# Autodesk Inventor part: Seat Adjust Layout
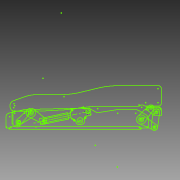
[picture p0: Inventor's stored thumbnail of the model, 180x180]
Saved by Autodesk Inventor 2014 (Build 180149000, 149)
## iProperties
Created: 2008-08
Part Number: Seat Adjust Layout
Document SubType Name: Modeling
Designer: hendert
Density: 1 g/cm^3
Material: Generic
Appearance: Default
d13: 10.000 mm
d14: 9.000 mm
d15: 10.000 mm
d16: 8.000 mm
d17: 46.000 mm
d19: 12.000 mm
d20: 85.000 mm
d23: 79.63 deg
d4: 14.000 mm
d5: 15.840 mm
d6: 9.000 mm
d7: 9.000 mm
d24: 121.84 deg
Author: hendert
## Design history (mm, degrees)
node "Blocks"
sketch "Sketch1"
  geometry: 3 further points
  constraints: 1 other
sketch "Pivot Plate"
  geometry: L1 (-47.957, 8.949)-(-1.489, 13.921); L2 (-1.489, -13.921)-(-47.957, -8.949); C1 r 4.5 at (-47, 0); C2 r 7.92 at (0, 0); A1 r 14 centre (0, 0) between (-1.489, -13.921) and (-1.489, 13.921); A2 r 9 centre (-47, 0) between (-47.957, 8.949) and (-47.957, -8.949); 1 further point
  constraints: 4 centre point, 4 end point, 4 point on circle, 4 tangent, 2 concentric, 1 horizontal alignment
  dimensions: "d4" = 14 radius of A1; "d5" = 15.84 diameter of C2; "d6" = 9 diameter of C1; "d7" = 9 radius of A2
sketch "Servo Motor"
  geometry: L1 (53.813, 25.723)-(28.281, 25.723); L2 (41, 0.723)-(53.813, 0.723); L3 (-18.847, -0.478)-(-18.034, -0.478); L4 (-18.034, -0.478)-(-18.034, 9.476); L5 (-20.625, -3.324)-(-20.625, -2.256); L6 (-18.034, -5.102)-(-18.847, -5.102); L7 (0, 17.459)-(0, -8.429); L8 (-18.034, -8.429)-(-18.034, -5.102); L9 (-1.27, -9.699)-(-16.764, -9.699); L10 (-18.034, 9.476)-(-18.847, 9.476); L11 (-20.625, 11.254)-(-20.625, 12.322); L12 (-18.847, 14.1)-(-18.288, 14.1); L13 (-18.034, 14.354)-(-18.034, 17.459); L14 (-17.247, 18.793)-(-17.247, 18.859); L15 (-17.247, 18.859)-(-17.247, 19.568); L16 (-17.247, 19.568)-(-17.247, 22.381); L17 (-17.247, 22.381)-(-17.247, 22.635); L18 (-0.991, 18.859)-(-0.991, 18.698); L19 (-0.991, 19.568)-(-0.991, 18.859); L20 (-0.991, 22.381)-(-0.991, 19.568); L21 (-0.991, 22.635)-(-0.991, 22.381); L22 (-0.991, 22.635)-(-17.247, 22.635); L23 (40, -1.438)-(40, -5.808); L24 (40, -1.438)-(40, 0); C1 r 7.92 at (53.813, 13.223); C2 r 4 at (20, 4.5); A1 r 1 centre (41, -0.277) between (41, 0.723) and (40, -0.277); A2 r 12.5 centre (53.813, 13.223) between (53.813, 0.723) and (53.813, 25.723); A3 r 1.778 centre (-18.847, -2.256) between (-18.847, -0.478) and (-20.625, -2.256); A4 r 1.778 centre (-18.847, -3.324) between (-20.625, -3.324) and (-18.847, -5.102); A5 r 1.27 centre (-16.764, -8.429) between (-18.034, -8.429) and (-16.764, -9.699); A6 r 1.27 centre (-1.27, -8.429) between (-1.27, -9.699) and (0, -8.429); A7 r 1.778 centre (-18.847, 11.254) between (-20.625, 11.254) and (-18.847, 9.476); A8 r 1.778 centre (-18.847, 12.322) between (-18.847, 14.1) and (-20.625, 12.322); A9 r 0.254 centre (-18.288, 14.354) between (-18.288, 14.1) and (-18.034, 14.354); A10 r 1.27 centre (-16.764, 17.459) between (-17.982, 17.818) and (-18.034, 17.459); A11 r 0.254 centre (-17.501, 18.793) between (-17.378, 18.571) and (-17.268, 18.693); A12 r 0.254 centre (-17.501, 18.793) between (-17.268, 18.693) and (-17.247, 18.793); A13 r 1.27 centre (-16.764, 17.459) between (-17.378, 18.571) and (-17.452, 18.527); A14 r 22.5 centre (20, 4.5) between (0, -5.808) and (40, -5.808); A15 r 22.5 centre (20, 4.5) between (26.776, 25.956) and (0, 14.808); A16 r 1.27 centre (-1.27, 17.459) between (-0.582, 18.527) and (-0.969, 18.693); A17 r 1.27 centre (-1.27, 17.459) between (-0.969, 18.693) and (-0.991, 18.698); A18 r 1.27 centre (-1.27, 17.459) between (0, 17.459) and (-0.052, 17.818); 3 further points; 1 other entity
  constraints: 48 end point, 36 point on circle, 20 centre point, 1 parallel, 10 other
sketch "Link Plate"
  geometry: L1 (-46, 10)-(0, 10); L2 (0, -10)-(-46, -10); C1 r 4.5 at (0, 0); C2 r 4 at (-46, 0); A1 r 10 centre (0, 0) between (0, -10) and (0, 10); A2 r 10 centre (-46, 0) between (-46, 10) and (-46, -10); 1 further point
  constraints: 4 centre point, 4 end point, 4 point on circle, 4 tangent, 2 concentric, 1 horizontal alignment
  dimensions: "d13" = 10 radius of A1; "d14" = 9 diameter of C1; "d15" = 10 radius of A2; "d16" = 8 diameter of C2; "d17" = 46 distance of C1.centre C2.centre
sketch "Worm Gear Assy_Front"
  geometry: L1 (-26, 39.15)-(-21, 39.15); L2 (-27, 32.15)-(-27, 38.15); L3 (-20, 43.15)-(-20, 40.15); L4 (-18, 32.15)-(-18.05, 32.15); L5 (0.05, 32.15)-(0, 32.15); L6 (2, 40.15)-(2, 43.15); L7 (1, 44.15)-(-19, 44.15); L8 (-10.236, -9.475)-(-10.236, 161.29); L9 (-27, 32.15)-(-27, 6.15); L10 (-21, -0.85)-(-26, -0.85); L11 (-20, -1.85)-(-20, -16.85); L12 (-19, -17.85)-(1, -17.85); L13 (2, -16.85)-(2, -1.85); L14 (8, -0.85)-(3, -0.85); L15 (9, 5.15)-(9, 0.15); L16 (-18.05, 6.15)-(-18, 6.15); L17 (0, 6.15)-(0.05, 6.15); L18 (-27, 0.15)-(-27, 6.15); L19 (10, 6.15)-(14, 6.15); L20 (24, 16.15)-(24, 22.15); L21 (3, 39.15)-(8, 39.15); L22 (9, 38.15)-(9, 33.15); L23 (14, 32.15)-(10, 32.15); L24 (-4.236, 44.15)-(-4.236, 129.15); L25 (-4.236, 129.15)-(-16.236, 129.15); L26 (-16.236, 129.15)-(-16.236, 44.15); C1 r 1.7 at (-23.5, 35.65); C2 r 1.7 at (-23.5, 2.65); C3 r 1.7 at (5.5, 2.65); C4 r 6 at (-10.236, -9.475); C5 r 1.7 at (5.5, 35.65); C6 r 8.5 at (11, 19.15); A1 r 1 centre (-19, 43.15) between (-19, 44.15) and (-20, 43.15); A2 r 1 centre (-21, 40.15) between (-21, 39.15) and (-20, 40.15); A3 r 1 centre (-26, 38.15) between (-26, 39.15) and (-27, 38.15); A4 r 1 centre (3, 40.15) between (2, 40.15) and (3, 39.15); A5 r 1 centre (1, 43.15) between (2, 43.15) and (1, 44.15); A6 r 1 centre (3, -1.85) between (3, -0.85) and (2, -1.85); A7 r 1 centre (-21, -1.85) between (-20, -1.85) and (-21, -0.85); A8 r 1 centre (-26, 0.15) between (-27, 0.15) and (-26, -0.85); A9 r 1 centre (-19, -16.85) between (-20, -16.85) and (-19, -17.85); A10 r 1 centre (1, -16.85) between (1, -17.85) and (2, -16.85); A11 r 1 centre (8, 0.15) between (8, -0.85) and (9, 0.15); A12 r 1 centre (10, 5.15) between (10, 6.15) and (9, 5.15); A13 r 10 centre (14, 16.15) between (14, 6.15) and (24, 16.15); A14 r 10 centre (14, 22.15) between (24, 22.15) and (14, 32.15); A15 r 1 centre (8, 38.15) between (9, 38.15) and (8, 39.15); A16 r 1 centre (10, 33.15) between (9, 33.15) and (10, 32.15); 1 further point
  constraints: 52 end point, 32 point on circle, 22 centre point, 3 perpendicular, 2 parallel, 2 point on line
  dimensions: "d19" = 12 diameter of L24 L8; "d20" = 85 distance between parallel lines of L7 L25
sketch "Connecting Rod"
  geometry: L1 (-9.682, 44)-(9.682, 44); L2 (-10, -44)-(10, -44); L3 (10, -44)-(10, -18); L4 (-10, -44)-(-10, -18); L5 (0, -44)-(0, 32.297); L6 (-9.682, 44)-(-9.682, -18); L7 (9.682, 44)-(9.682, -18); L8 (10, -18)-(9.682, -18); L9 (-10, -18)-(-9.682, -18); 3 further points
  constraints: 18 end point, 3 parallel, 2 perpendicular, 1 midpoint, 1 other
sketch "Seat Pan"
  geometry: L1 (206.698, 35.831)-(145.708, 32.634); L2 (258.23, 34.968)-(258.23, 37.468); L3 (262.23, 37.468)-(258.23, 37.468); L4 (258.23, 48.488)-(258.23, 43.468); L5 (155.903, -13.987)-(234.265, -13.987); L6 (258.23, 43.468)-(258.23, 37.468); L7 (-150.687, 12.124)-(-150.687, -30.876); L8 (-102.176, 22.124)-(-140.687, 22.124); L9 (-103.081, 25.124)-(-103.081, 22.124); L10 (-103.081, 25.124)-(-143.081, 25.124); L11 (-143.081, 25.124)-(-143.081, 22.124); L12 (-110.904, 27.624)-(-142.187, 27.624); L13 (-142.187, 25.124)-(-110.904, 25.124); L14 (-102.404, 34.26)-(-102.404, 33.624); L15 (-104.904, 33.624)-(-104.904, 34.26); L16 (-105.934, 34.26)-(-102.404, 34.26); L17 (-110.904, 37.235)-(-108.524, 35.213); L18 (-126.284, 50.308)-(-110.904, 37.235); L19 (-30.219, 22.124)-(-81.969, 22.124); L20 (43.085, -33.968)-(97.541, -20.894); L21 (-15.276, -40.876)-(-30.219, -40.876); L22 (-140.687, -40.876)-(-30.219, -40.876); L23 (262.23, 37.468)-(299.73, 37.468); L24 (267.398, -8.339)-(305.104, 4.902); L25 (309.982, 8.602)-(312.273, 11.873); L26 (313.58, 26.816)-(312.005, 30.194); L27 (142.927, 32.391)-(66.598, 23.019); L28 (-30.219, 22.124)-(-22.863, 22.124); L29 (-17.687, 22.124)-(-22.863, 22.124); L30 (-10.616, 22.124)-(-17.687, 22.124); L31 (9.242, 22.124)-(-10.616, 22.124); L32 (16.313, 22.124)-(9.242, 22.124); L33 (21.384, 22.124)-(16.313, 22.124); L34 (51.974, 22.124)-(21.905, 22.124); L35 (21.905, 22.124)-(21.384, 22.124); L36 (305.73, 49.968)-(305.73, 45.968); L37 (305.73, 43.468)-(305.73, 45.968); L38 (308.23, 43.468)-(308.23, 45.968); L39 (308.23, 45.968)-(308.23, 49.968); L40 (305.73, 49.968)-(308.23, 49.968); L41 (308.23, 53.968)-(308.23, 49.968); L42 (305.73, 49.968)-(305.73, 53.968); L43 (-142.187, 51.26)-(-128.874, 51.26); L44 (-142.187, 51.26)-(-128.874, 51.26); L45 (-148.187, 34.26)-(-148.187, 33.624); L46 (-148.187, 34.26)-(-150.687, 34.26); L47 (-150.687, 34.26)-(-150.687, 35.701); L48 (-145.613, 51.26)-(-142.187, 51.26); L49 (-149.114, 51.26)-(-142.187, 51.26); L50 (-150.636, 38.26)-(-150.636, 47.26); L51 (211.932, 35.968)-(302.942, 35.968); L52 (259.193, 51.091)-(287.033, 83.571); L53 (296.13, 84.968)-(290.07, 84.968); L54 (308.23, 53.968)-(308.23, 69.444); L55 (305.73, 71.825)-(305.73, 53.968); L56 (308.23, 69.444)-(308.23, 74.968); L57 (305.73, 77.349)-(305.73, 71.825); L58 (308.23, 74.968)-(299.73, 83.063); L59 (299.73, 83.063)-(305.73, 77.349); L60 (298.889, 83.864)-(299.73, 83.063); C1 r 5 at (-135.024, 41.104); C2 r 6 at (287.445, 69.968); A1 r 40 centre (147.801, -7.311) between (145.708, 32.634) and (142.927, 32.391); A2 r 4 centre (262.23, 48.488) between (259.193, 51.091) and (258.23, 48.488); A3 r 100 centre (234.265, 86.013) between (234.265, -13.987) and (267.398, -8.339); A4 r 100 centre (211.932, -64.032) between (211.932, 35.968) and (206.698, 35.831); A5 r 10 centre (-140.687, -30.876) between (-150.687, -30.876) and (-140.687, -40.876); A6 r 10 centre (-102.176, 12.124) between (-95.966, 19.962) and (-102.176, 22.124); A7 r 10 centre (-140.687, 12.124) between (-140.687, 22.124) and (-150.687, 12.124); A8 r 8.5 centre (-110.904, 33.624) between (-110.904, 25.124) and (-103.098, 30.26); A9 r 4 centre (-128.874, 47.26) between (-126.284, 50.308) and (-128.874, 51.26); A10 r 6 centre (-110.904, 33.624) between (-110.904, 27.624) and (-105.936, 30.26); A11 r 8.5 centre (-90.687, 26.624) between (-95.966, 19.962) and (-84.245, 21.079); A12 r 250 centre (155.903, -263.987) between (155.903, -13.987) and (97.541, -20.894); A13 r 250 centre (-15.276, 209.124) between (0.312, -40.389) and (43.085, -33.968); A14 r 10 centre (301.79, 14.337) between (305.104, 4.902) and (309.982, 8.602); A15 r 10 centre (302.942, 25.968) between (312.005, 30.194) and (302.942, 35.968); A16 r 15 centre (299.986, 20.477) between (312.273, 11.873) and (313.58, 26.816); A17 r 120 centre (51.974, 142.124) between (51.974, 22.124) and (66.598, 23.019); A18 r 6 centre (299.73, 43.468) between (299.73, 37.468) and (305.73, 43.468); A19 r 8.5 centre (299.73, 43.468) between (299.73, 34.968) and (308.23, 43.468); A20 r 6 centre (-142.187, 33.624) between (-147.155, 30.26) and (-142.187, 27.624); A21 r 8.5 centre (-142.187, 33.624) between (-149.993, 30.26) and (-142.187, 25.124); A22 r 4 centre (290.07, 80.968) between (290.07, 84.968) and (287.033, 83.571); A23 r 4 centre (296.13, 80.968) between (298.889, 83.864) and (296.13, 84.968); 4 further points; 1 other entity
  constraints: 120 end point, 46 point on circle, 25 centre point, 24 other
sketch "Seat Slider"
  geometry: L1 (331.944, 57.592)-(386.835, 57.592); L2 (272.222, 48.283)-(330.067, 57.445); L3 (246.8, 59.962)-(264.306, 49.766); L4 (204, 61.592)-(240.76, 61.592); L5 (398, 5.45)-(4, 5.45); L6 (402, 0)-(402, -4); L7 (402, -4)-(0, -4); L8 (46.182, 57.622)-(204, 61.592); L9 (-2.638, 46.859)-(43.846, 57.332); L10 (-12, 6.75)-(-12, 35.153); L11 (0, 1.45)-(0, 0); L12 (0, -0.861)-(0, -2); L13 (0, -4)-(0, 0); L14 (-12, 6.75)-(-12, 5.259); L15 (-10, 1.139)-(-2, 1.139); L16 (-12, 3.139)-(-12, 5.259); L17 (402, 0)-(402, 1.45); L18 (392.753, 56.031)-(418.918, 41.198); L19 (425, 30.759)-(425, 6.75); L20 (425, 6.75)-(425, 5.259); L21 (425, 3.139)-(425, 5.259); L22 (404, 1.139)-(423, 1.139); C1 r 6.33 at (239.283, 51.062); A1 r 12 centre (386.835, 45.592) between (392.753, 56.031) and (386.835, 57.592); A2 r 12 centre (331.944, 45.592) between (331.944, 57.592) and (330.067, 57.445); A3 r 12 centre (240.76, 49.592) between (246.8, 59.962) and (240.76, 61.592); A4 r 12 centre (270.345, 60.135) between (264.306, 49.766) and (272.222, 48.283); A5 r 4.18 centre (64.92, 47.922) between (69.099, 48.024) and (69.099, 47.821); A6 r 12 centre (46.484, 45.626) between (46.182, 57.622) and (43.846, 57.332); A7 r 12 centre (0, 35.153) between (-2.638, 46.859) and (-12, 35.153); A8 r 4 centre (4, 1.45) between (4, 5.45) and (0, 1.45); A9 r 2 centre (-2, -0.861) between (-0.195, 0) and (-2, 1.139); A10 r 2 centre (-10, 3.139) between (-11.805, 2.278) and (-10, 1.139); A11 r 4 centre (398, 1.45) between (402, 1.45) and (398, 5.45); A12 r 4.18 centre (403.103, 27.042) between (407.282, 27.144) and (407.282, 26.941); A13 r 2 centre (404, -0.861) between (404, 1.139) and (402.195, 0); A14 r 12 centre (413, 30.759) between (425, 30.759) and (418.918, 41.198); A15 r 2 centre (423, 3.139) between (423, 1.139) and (424.805, 2.278); 1 further point
  constraints: 44 end point, 30 point on circle, 16 centre point, 3 other
sketch "Screw Rod Assy_Front"
  geometry: 1 further point
sketch "Front Pivot Weldment" dims "d23" = 79.63 deg
  geometry: 1 further point
sketch "Rear Pivot Weldment" dims "d24" = 121.84 deg
  geometry: 1 further point
sketch "Worm Gear Assy_Rear"
  geometry: L1 (-620.183, 266.776)-(-620.233, 266.776); L2 (-602.133, 266.776)-(-602.183, 266.776); L3 (-593.183, 260.776)-(-593.183, 266.776); L4 (-599.183, 259.776)-(-594.183, 259.776); L5 (-594.183, 299.776)-(-599.183, 299.776); L6 (-593.183, 292.776)-(-593.183, 298.776); L7 (-593.183, 292.776)-(-593.183, 266.776); L8 (-602.183, 292.776)-(-602.133, 292.776); L9 (-609.947, 251.151)-(-609.947, 421.916); L10 (-615.947, 304.776)-(-615.947, 389.776); L11 (-603.947, 389.776)-(-603.947, 304.776); L12 (-630.183, 266.776)-(-634.183, 266.776); L13 (-634.183, 292.776)-(-630.183, 292.776); L14 (-644.183, 276.776)-(-644.183, 282.776); L15 (-620.233, 292.776)-(-620.183, 292.776); L16 (-623.183, 299.776)-(-628.183, 299.776); L17 (-629.183, 298.776)-(-629.183, 293.776); L18 (-615.947, 389.776)-(-603.947, 389.776); L19 (-600.183, 303.776)-(-600.183, 300.776); L20 (-621.183, 304.776)-(-601.183, 304.776); L21 (-622.183, 300.776)-(-622.183, 303.776); L22 (-600.183, 258.776)-(-600.183, 243.776); L23 (-601.183, 242.776)-(-621.183, 242.776); L24 (-628.183, 259.776)-(-623.183, 259.776); L25 (-622.183, 243.776)-(-622.183, 258.776); L26 (-629.183, 265.776)-(-629.183, 260.776); C1 r 1.7 at (-596.683, 263.276); C2 r 1.7 at (-596.683, 296.276); C3 r 8.5 at (-631.183, 279.776); C4 r 1.7 at (-625.683, 296.276); C5 r 6 at (-609.947, 251.151); C6 r 1.7 at (-625.683, 263.276); A1 r 1 centre (-599.183, 258.776) between (-599.183, 259.776) and (-600.183, 258.776); A2 r 1 centre (-594.183, 260.776) between (-594.183, 259.776) and (-593.183, 260.776); A3 r 1 centre (-594.183, 298.776) between (-593.183, 298.776) and (-594.183, 299.776); A4 r 10 centre (-634.183, 276.776) between (-644.183, 276.776) and (-634.183, 266.776); A5 r 10 centre (-634.183, 282.776) between (-634.183, 292.776) and (-644.183, 282.776); A6 r 1 centre (-623.183, 300.776) between (-623.183, 299.776) and (-622.183, 300.776); A7 r 1 centre (-628.183, 298.776) between (-628.183, 299.776) and (-629.183, 298.776); A8 r 1 centre (-630.183, 293.776) between (-630.183, 292.776) and (-629.183, 293.776); A9 r 1 centre (-599.183, 300.776) between (-600.183, 300.776) and (-599.183, 299.776); A10 r 1 centre (-601.183, 303.776) between (-600.183, 303.776) and (-601.183, 304.776); A11 r 1 centre (-621.183, 303.776) between (-621.183, 304.776) and (-622.183, 303.776); A12 r 1 centre (-601.183, 243.776) between (-601.183, 242.776) and (-600.183, 243.776); A13 r 1 centre (-630.183, 265.776) between (-629.183, 265.776) and (-630.183, 266.776); A14 r 1 centre (-628.183, 260.776) between (-629.183, 260.776) and (-628.183, 259.776); A15 r 1 centre (-623.183, 258.776) between (-622.183, 258.776) and (-623.183, 259.776); A16 r 1 centre (-621.183, 243.776) between (-622.183, 243.776) and (-621.183, 242.776); 1 further point
  constraints: 52 end point, 32 point on circle, 22 centre point, 2 point on line
sketch "Screw Rod Assy_Rear"
  geometry: 1 further point
node "Link Plate:1"
node "Link Plate:2"
node "Worm Gear Assy_Front:2"
node "Connecting Rod:2"
node "Seat Pan:1"
node "Front Pivot Weldment:1"
node "Pivot Plate:7" dims angle "d23" = 79.63 deg
node "Pivot Plate:8" dims angle "d23" = 79.63 deg
node "Pivot Plate:9" dims angle "d23" = 79.63 deg
node "Rear Pivot Weldment:1"
node "Pivot Plate:10" dims angle "d24" = 121.84 deg
node "Pivot Plate:11" dims angle "d24" = 121.84 deg
node "Pivot Plate:12" dims angle "d24" = 121.84 deg
node "Seat Slider:1"
node "Screw Rod Assy_Rear:1"
node "Connecting Rod:4"
node "Worm Gear Assy_Rear:2"
